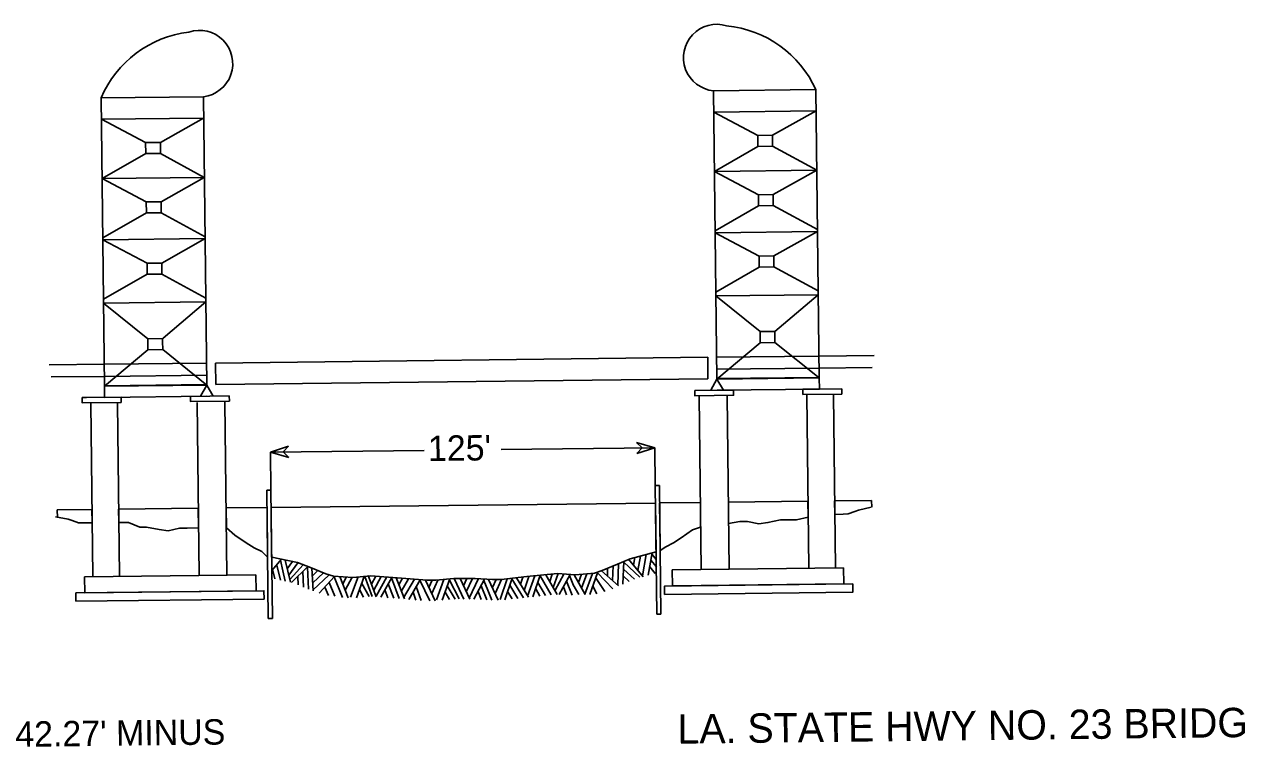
# Model space of a CAD drawing. Extents: x 3683402 to 3721514, y 487807 to 513565.
# Drawn here: x 3690742 to 3695530, y 507301 to 510168 of the extents above; entities that cross this region are included whole.
import ezdxf

# ---------------------------------------------------------------- set-up
doc = ezdxf.new("R2010")
doc.units = 0
doc.layers.add('V-ANNO-SYMB', color=7, linetype='Continuous')

msp = doc.modelspace()

# ---------------------------------------------------------------- linework, layer by layer
at = {"layer": 'V-ANNO-SYMB'}
for p, q in [((3693863.4, 509910.7), (3693460.2, 509906)), ((3693473.4, 508769.8), (3693460.2, 509906)), ((3693876.6, 508774.4), (3693863.4, 509910.7)), ((3691045.2, 509878), (3691448.4, 509882.7)), ((3691058.4, 508741.7), (3691045.2, 509878)), ((3691461.6, 508746.4), (3691448.4, 509882.7)), ((3693864.3, 509826.8), (3693461.1, 509822.1)), ((3693634, 509730.2), (3693461.1, 509822.1)), ((3693864.3, 509826.8), (3693692.1, 509730.8)), ((3691046.2, 509794.1), (3691449.4, 509798.8)), ((3691046.2, 509794.1), (3691220.6, 509702.1)), ((3691278.7, 509702.8), (3691449.4, 509798.8)), ((3691048.9, 509560.2), (3691221.1, 509658.7)), ((3691279.2, 509659.3), (3691452.1, 509564.9)), ((3693634.5, 509686.7), (3693463.8, 509588.3)), ((3693867.1, 509593), (3693692.6, 509687.4)), ((3691048.9, 509560.2), (3691452.1, 509564.9)), ((3691281.4, 509468.9), (3691452.1, 509564.9)), ((3693867.1, 509593), (3693463.8, 509588.3)), ((3693636.7, 509496.3), (3693463.8, 509588.3)), ((3693867.1, 509593), (3693694.8, 509497)), ((3691048.9, 509560.2), (3691223.4, 509468.2)), ((3691051.6, 509326.3), (3691223.9, 509424.8)), ((3691281.9, 509425.5), (3691454.8, 509331)), ((3693637.2, 509452.8), (3693466.6, 509354.4)), ((3693869.8, 509359.1), (3693695.3, 509453.5)), ((3691051.7, 509318.6), (3691454.9, 509323.3)), ((3691284.2, 509227.3), (3691454.9, 509323.3)), ((3693869.9, 509351.4), (3693466.7, 509346.7)), ((3693639.5, 509254.7), (3693466.7, 509346.7)), ((3693869.9, 509351.4), (3693697.6, 509255.4)), ((3691051.7, 509318.6), (3691226.2, 509226.7)), ((3691054.4, 509084.8), (3691226.7, 509183.2)), ((3691284.8, 509183.9), (3691457.6, 509089.4)), ((3693640, 509211.3), (3693469.4, 509112.8)), ((3693872.6, 509117.5), (3693698.1, 509211.9)), ((3693872.8, 509102.3), (3693469.5, 509097.7)), ((3693643.1, 508956.8), (3693469.5, 509097.7)), ((3693872.8, 509102.3), (3693701.2, 508957.5)), ((3691054.6, 509069.6), (3691457.8, 509074.3)), ((3691054.6, 509069.6), (3691229.5, 508928.7)), ((3691290.1, 508931.5), (3691457.8, 509074.3)), ((3693643.6, 508913.3), (3693473.4, 508769.8)), ((3693876.6, 508774.4), (3693701.7, 508914)), ((3691058.4, 508741.7), (3691230, 508885.3)), ((3691288.1, 508886), (3691461.6, 508746.4)), ((3691496.2, 508833.1), (3693436.8, 508855.6)), ((3693436.8, 508855.6), (3691496.2, 508833.1)), ((3693436.8, 508855.6), (3693437.8, 508771.1)), ((3693436.8, 508855.6), (3693437.8, 508771.1)), ((3693469.3, 508856), (3693875.6, 508860.7)), ((3693875.6, 508860.7), (3694092.6, 508863.2)), ((3694092.6, 508863.2), (3693875.6, 508860.7)), ((3691057.4, 508828), (3690840.4, 508825.4)), ((3690840.4, 508825.4), (3691057.4, 508828)), ((3691461.6, 508832.7), (3691057.4, 508828)), ((3691496.2, 508833.1), (3691497.2, 508748.5)), ((3691496.2, 508833.1), (3691497.2, 508748.5)), ((3693469.9, 508808.5), (3693876.1, 508813.3)), ((3693876.1, 508813.3), (3694085.9, 508815.7)), ((3691058, 508780.5), (3690848.2, 508778.1)), ((3691462.2, 508785.2), (3691058, 508780.5)), ((3691462.6, 508748.1), (3691058.4, 508743.4)), ((3691497.2, 508748.5), (3693437.8, 508771.1)), ((3693437.8, 508771.1), (3691497.2, 508748.5)), ((3693473.4, 508769.8), (3693449.2, 508725.5)), ((3693470.3, 508771.5), (3693876.6, 508776.2)), ((3693876.6, 508774.4), (3693473.4, 508769.8)), ((3693473.4, 508769.8), (3693498.6, 508726.1)), ((3693876.6, 508774.4), (3693877.1, 508730.5)), ((3691058.4, 508741.7), (3691461.6, 508746.4)), ((3691058.4, 508741.7), (3691058.9, 508697.7)), ((3691058.9, 508697.7), (3691462.1, 508702.4)), ((3691461.6, 508746.4), (3691437.4, 508702.1)), ((3691461.6, 508746.4), (3691486.9, 508702.7)), ((3693403, 508701), (3693411, 508019.1)), ((3693877.1, 508730.5), (3693473.9, 508725.8)), ((3693513.3, 508702.3), (3693521.2, 508020.4)), ((3693827.2, 508705.9), (3693835.1, 508024)), ((3693932.3, 508707.2), (3693940.3, 508025.3)), ((3693965.5, 508731.5), (3693965.7, 508711)), ((3691004.2, 508673.1), (3691012.2, 507991.2)), ((3691109.4, 508674.3), (3691117.3, 507992.5)), ((3691423.3, 508678), (3691431.2, 507996.1)), ((3691533.5, 508679.3), (3691541.5, 507997.4)), ((3693156.3, 508520.4), (3693178.4, 508498.8)), ((3693228.4, 508499.5), (3693156.3, 508520.4)), ((3693156.3, 508520.4), (3693178.4, 508498.8)), ((3693228.4, 508499.5), (3693156.3, 508520.4)), ((3691783.9, 508505.1), (3691712.8, 508481.9)), ((3691783.9, 508505.1), (3691712.8, 508481.9)), ((3691712.8, 508481.9), (3692318.4, 508488.9)), ((3691712.8, 508481.9), (3691727.6, 508482)), ((3691714.5, 508332.6), (3691712.8, 508481.9)), ((3691712.8, 508481.9), (3691784.9, 508461)), ((3691712.8, 508481.9), (3691784.9, 508461)), ((3691762.8, 508482.5), (3691783.9, 508505.1)), ((3691762.8, 508482.5), (3691783.9, 508505.1)), ((3691784.9, 508461), (3691762.8, 508482.5)), ((3691784.9, 508461), (3691762.8, 508482.5)), ((3692621.9, 508492.4), (3693228.4, 508499.5)), ((3693157.3, 508476.3), (3693228.4, 508499.5)), ((3693157.3, 508476.3), (3693228.4, 508499.5)), ((3693178.4, 508498.8), (3693157.3, 508476.3)), ((3693178.4, 508498.8), (3693157.3, 508476.3)), ((3693230.2, 508350.2), (3693228.4, 508499.5)), ((3691698.5, 508332.4), (3691714.5, 508332.6)), ((3691704.4, 507825.7), (3691698.5, 508332.4)), ((3691720.4, 507825.9), (3691714.5, 508332.6)), ((3693246.2, 508350.4), (3693230.2, 508350.2)), ((3693236.1, 507843.5), (3693230.2, 508350.2)), ((3693252.1, 507843.7), (3693246.2, 508350.4)), ((3691715.3, 508263.8), (3693231, 508281.4)), ((3693231, 508281.4), (3691715.3, 508263.8)), ((3693233.2, 508088.5), (3693231, 508281.4)), ((3693247, 508281.6), (3693407.9, 508283.5)), ((3693247, 508281.6), (3693407.9, 508283.5)), ((3693249, 508103.5), (3693247, 508281.6)), ((3693407.9, 508283.5), (3693409, 508186.4)), ((3693518.2, 508284.7), (3693832, 508288.4)), ((3693832, 508288.4), (3693518.2, 508284.7)), ((3693518.2, 508284.7), (3693519.1, 508200.3)), ((3693832.7, 508225.3), (3693832, 508288.4)), ((3693937.2, 508289.6), (3694083.2, 508291.3)), ((3694083.2, 508291.3), (3693937.2, 508289.6)), ((3693937.2, 508289.6), (3693937.8, 508236.7)), ((3694083.5, 508264.4), (3694083.2, 508291.3)), ((3690872.5, 508254), (3691009.1, 508255.6)), ((3690872.5, 508254), (3691009.1, 508255.6)), ((3690872.8, 508223.8), (3690872.5, 508254)), ((3691009.1, 508255.6), (3691009.7, 508203.5)), ((3691114.3, 508256.8), (3691428.1, 508260.4)), ((3691428.1, 508260.4), (3691114.3, 508256.8)), ((3691114.3, 508256.8), (3691114.9, 508204.2)), ((3691429, 508183.1), (3691428.1, 508260.4)), ((3691538.4, 508261.7), (3691699.3, 508263.6)), ((3691699.3, 508263.6), (3691538.4, 508261.7)), ((3691538.4, 508261.7), (3691539.3, 508183.2)), ((3691701.6, 508069.3), (3691699.3, 508263.6)), ((3691715.3, 508263.8), (3691717.6, 508068)), ((3693194.7, 508078.3), (3693179.4, 507994.2)), ((3693218.1, 508084.5), (3693202.4, 507996.4)), ((3693217.2, 508079), (3693234.1, 508058.7)), ((3693249, 508103.5), (3693249.2, 508093.6)), ((3691755.9, 508060), (3691718.2, 508015.4)), ((3691738.3, 508036.3), (3691752, 507977.7)), ((3691752.6, 508055.5), (3691762.2, 508014.3)), ((3691771.2, 508056.7), (3691791.3, 507969.5)), ((3691800.1, 508050.7), (3691779.2, 508022.3)), ((3691821.1, 508046.2), (3691785, 507997.4)), ((3691841.7, 508038.1), (3691790.6, 507981.3)), ((3691860.6, 508030.8), (3691796.1, 507968.3)), ((3691858.5, 508029.1), (3691863, 507942.4)), ((3693063.5, 508033.3), (3693062.1, 507975.3)), ((3693084.8, 508042.5), (3693082.4, 507957.4)), ((3693105.6, 508051.1), (3693101.9, 507961.6)), ((3693105.5, 508048.6), (3693169.5, 507989.6)), ((3693124.9, 508060), (3693182.1, 507991)), ((3693150, 508066.6), (3693144.7, 508036.3)), ((3693172.2, 508072.4), (3693161.9, 508015.2)), ((3693208.4, 508030), (3693230, 508003.6)), ((3693212.9, 508055.5), (3693234.5, 508029.6)), ((3690979.9, 507990.9), (3691655.6, 507998.7)), ((3690979.9, 507990.9), (3690980.6, 507927.4)), ((3691655.6, 507998.7), (3691656.3, 507935.3)), ((3691722.8, 508015.6), (3691730.3, 507982.3)), ((3691762.2, 508014.3), (3691771.5, 507973.6)), ((3691820.5, 507992.2), (3691822.5, 507958.4)), ((3691839.9, 508010.9), (3691843.7, 507950.2)), ((3691876.5, 508024.5), (3691881.5, 507934.9)), ((3691899.9, 508015.1), (3691878.3, 507994.4)), ((3691921.9, 508006.2), (3691879.7, 507966.4)), ((3691943.5, 507997.5), (3691881.3, 507939.3)), ((3691965.2, 507991.6), (3691904.5, 507925.7)), ((3691964.2, 507990.2), (3691996.4, 507909.3)), ((3691986.5, 507991.2), (3692019.8, 507908)), ((3692012.4, 507989.8), (3691998.1, 507962.6)), ((3692035.4, 507988.6), (3692008, 507937.2)), ((3692058.5, 507990.2), (3692029, 507910)), ((3692082.7, 507992.2), (3692051.9, 507908.1)), ((3692084.6, 507992.3), (3692114.3, 507913.4)), ((3692098.2, 507995), (3692129.9, 507911.3)), ((3692127.7, 507992.9), (3692110.8, 507962)), ((3692149.1, 507991.4), (3692120, 507938)), ((3692171.2, 507989.8), (3692129.4, 507913.8)), ((3692191.4, 507988.3), (3692148, 507909.7)), ((3692189.9, 507985.9), (3692220.8, 507904.8)), ((3692208.5, 507987.1), (3692240.7, 507903.3)), ((3692233.7, 507985.3), (3692219.4, 507959)), ((3692257.3, 507983.1), (3692228.5, 507932.7)), ((3692280.4, 507981.1), (3692237.9, 507907.3)), ((3692420, 507982.2), (3692390.1, 507897.8)), ((3692438.5, 507981.3), (3692474.8, 507902.2)), ((3692460.7, 507983.5), (3692498.3, 507902.1)), ((3692486.7, 507983.4), (3692473.7, 507955.5)), ((3692509.7, 507983.4), (3692485, 507930.7)), ((3692532.9, 507983.3), (3692496.5, 507905.9)), ((3692557.1, 507981.3), (3692515.2, 507902.2)), ((3692645.7, 507982.6), (3692618.3, 507900.4)), ((3692665.8, 507984.9), (3692637.4, 507899.7)), ((3692664.8, 507982.2), (3692709.9, 507908.1)), ((3692682.8, 507986.8), (3692729.7, 507910.3)), ((3692707.9, 507989.6), (3692698.6, 507961.1)), ((3692731.5, 507992.2), (3692713.2, 507937.1)), ((3692754.6, 507994.3), (3692726.2, 507914)), ((3692776.9, 507996.4), (3692747.2, 507912)), ((3692776.2, 507994.1), (3692820.1, 507918.9)), ((3692798, 507998.4), (3692843.4, 507921.1)), ((3692823.9, 508000.9), (3692813.8, 507971.8)), ((3692846.8, 508003.1), (3692827.4, 507948.3)), ((3692870, 508001.3), (3692835.7, 507937.6)), ((3692894.1, 507999.9), (3692851.8, 507921)), ((3692891.6, 507995), (3692907.2, 507955.6)), ((3692909.8, 507998.2), (3692953.6, 507920.1)), ((3692939.2, 508000.5), (3692927.1, 507967.4)), ((3692960.6, 508002.2), (3692939.7, 507945.1)), ((3692982.7, 508003.9), (3692952.6, 507922.6)), ((3693002.8, 508005.5), (3692971.7, 507921.3)), ((3692994.8, 507987.4), (3693031.2, 507932)), ((3693001.9, 508005.7), (3693062.2, 507943.3)), ((3693018.5, 508014), (3693085.6, 507954.4)), ((3693041.7, 508024), (3693041.1, 507994)), ((3693103.7, 507994.8), (3693127.8, 507972.3)), ((3693104.4, 508020.8), (3693147.8, 507980.6)), ((3693972.5, 508025.6), (3693296.8, 508017.8)), ((3693296.8, 508017.8), (3693297.6, 507954.4)), ((3693972.5, 508025.6), (3693973.3, 507962.2)), ((3690980.6, 507927.4), (3691656.3, 507935.3)), ((3691927.4, 507949.9), (3691941.7, 507916.4)), ((3691944.6, 507968.6), (3691966.4, 507913.6)), ((3692063.7, 507940.2), (3692080.3, 507910.5)), ((3692072.5, 507964.5), (3692102.5, 507912.3)), ((3692164.3, 507939.7), (3692176.2, 507907.9)), ((3692177.4, 507963.3), (3692198.9, 507906.3)), ((3692302.8, 507979.1), (3692258.2, 507901.5)), ((3692287.8, 507952.8), (3692307.7, 507897.1)), ((3692301.6, 507976.9), (3692341.4, 507896)), ((3692323.9, 507976.6), (3692362.7, 507895.8)), ((3692349.9, 507976.9), (3692337.3, 507948.8)), ((3692372.8, 507977.2), (3692349, 507924.2)), ((3692395.9, 507979.9), (3692367.1, 507899.5)), ((3692410.2, 507954.4), (3692440.6, 507902.5)), ((3692418.2, 507976.9), (3692457.5, 507903.7)), ((3692543.3, 507955.3), (3692565.8, 507899.5)), ((3692554.5, 507976.4), (3692570.4, 507937.2)), ((3692570.4, 507937.2), (3692585.7, 507898.4)), ((3692572.7, 507979.5), (3692611.2, 507898.7)), ((3692602.2, 507979.9), (3692587.9, 507947.7)), ((3692623.6, 507980.1), (3692599, 507924.6)), ((3692656.6, 507957.7), (3692688.1, 507905.6)), ((3692758.7, 507943.2), (3692775.1, 507914.6)), ((3692767, 507967.9), (3692796.7, 507916.7)), ((3692868, 507951.2), (3692880.2, 507919.3)), ((3692880.2, 507973.9), (3692902.4, 507918)), ((3692906.1, 507958.5), (3692929, 507921.4)), ((3692983.4, 507953.4), (3692999.9, 507923.8)), ((3693973.3, 507962.2), (3693297.6, 507954.4)), ((3692275.1, 507930.1), (3692286.1, 507899)), ((3692401.5, 507930), (3692418.5, 507900.4)), ((3692531.2, 507932.4), (3692543.6, 507900.7)), ((3692648, 507932.1), (3692665.5, 507903.1)), ((3693252.1, 507843.7), (3693236.1, 507843.5)), ((3691704.4, 507825.7), (3691720.4, 507825.9))]:
    msp.add_line(p, q, dxfattribs=at)
for points in [[(3693692.1, 509730.8), (3693634, 509730.2), (3693634.5, 509686.7), (3693692.6, 509687.4), (3693692.1, 509730.8)], [(3691278.8, 509691.8), (3691279.2, 509659.3), (3691221.1, 509658.7), (3691220.6, 509702.1), (3691278.7, 509702.8), (3691278.8, 509691.8)], [(3691281.4, 509468.9), (3691281.9, 509425.5), (3691223.9, 509424.8), (3691223.4, 509468.2), (3691281.4, 509468.9)], [(3693694.8, 509497), (3693636.7, 509496.3), (3693637.2, 509452.8), (3693695.3, 509453.5), (3693694.8, 509497)], [(3691284.2, 509227.3), (3691284.8, 509183.9), (3691226.7, 509183.2), (3691226.2, 509226.7), (3691284.2, 509227.3)], [(3693697.6, 509255.4), (3693639.5, 509254.7), (3693640, 509211.3), (3693698.1, 509211.9), (3693697.6, 509255.4)], [(3693701.2, 508957.5), (3693643.1, 508956.8), (3693643.6, 508913.3), (3693701.7, 508914), (3693701.2, 508957.5)], [(3691287.8, 508918), (3691288.1, 508886), (3691230, 508885.3), (3691229.5, 508928.7), (3691287.6, 508929.4), (3691287.8, 508918)], [(3691550.5, 508703.4), (3691550.8, 508682.9), (3691397.6, 508681.1), (3691397.4, 508701.7), (3691550.5, 508703.4)], [(3693385.5, 508724.8), (3693385.7, 508704.2), (3693538.9, 508706), (3693538.6, 508726.6), (3693385.5, 508724.8)], [(3693965.7, 508711), (3693812.5, 508709.2), (3693812.3, 508729.7), (3693965.5, 508731.5)], [(3690987.6, 508696.9), (3690970.6, 508696.7), (3690970.8, 508676.1), (3691123.9, 508677.9), (3691123.7, 508698.5), (3690987.6, 508696.9)], [(3690865.3, 508227), (3690915.8, 508217.5), (3690931, 508212.7), (3690956.3, 508202.9), (3690976.4, 508203.1), (3691009.7, 508203.5)], [(3691009.7, 508203.5), (3690976.4, 508203.1), (3690956.3, 508202.9), (3690931, 508212.7), (3690915.8, 508217.5), (3690865.3, 508227)], [(3693832.7, 508225.3), (3693786.7, 508214.7), (3693749.5, 508215.2), (3693724.3, 508214.9), (3693674, 508204.2), (3693638.8, 508198.7), (3693593.3, 508208.3), (3693563.1, 508208), (3693519.1, 508200.3)], [(3693519.1, 508200.3), (3693563.1, 508208), (3693593.3, 508208.3), (3693638.8, 508198.7), (3693674, 508204.2), (3693724.3, 508214.9), (3693749.5, 508215.2), (3693786.7, 508214.7), (3693832.7, 508225.3)], [(3694081.7, 508264.4), (3694031.4, 508253.8), (3694016.3, 508248.5), (3693991.2, 508238.2), (3693971.1, 508237.9), (3693938.2, 508236.7)], [(3693938.2, 508236.7), (3693971.1, 508237.9), (3693991.2, 508238.2), (3694016.3, 508248.5), (3694031.4, 508253.8), (3694081.7, 508264.4)], [(3691114.9, 508204.2), (3691152.8, 508205.2), (3691198.4, 508185.5), (3691223.6, 508185.8), (3691274.2, 508176.3), (3691309.5, 508171.7), (3691354.8, 508182.3), (3691385, 508182.6), (3691429, 508183.1)], [(3691114.9, 508204.2), (3691152.8, 508205.2), (3691198.4, 508185.5), (3691223.6, 508185.8), (3691274.2, 508176.3), (3691309.5, 508171.7), (3691354.8, 508182.3), (3691385, 508182.6), (3691429, 508183.1)], [(3691539.3, 508183.2), (3691571.8, 508154.5), (3691617.6, 508124.8), (3691648, 508105), (3691678.5, 508090.2), (3691699.9, 508069.2)], [(3691539.3, 508183.2), (3691571.8, 508154.5), (3691617.6, 508124.8), (3691648, 508105), (3691678.5, 508090.2), (3691699.9, 508069.2)], [(3693409, 508186.4), (3693376.9, 508175.5), (3693331.9, 508144.7), (3693301.9, 508124.2), (3693271.8, 508108.7), (3693249.2, 508093.7)], [(3693409, 508186.4), (3693376.9, 508175.5), (3693331.9, 508144.7), (3693301.9, 508124.2), (3693271.8, 508108.7), (3693249.2, 508093.7)], [(3693233.2, 508088.5), (3693131.2, 508061.7), (3693081.1, 508040.9), (3693020.9, 508015), (3692990.8, 508004.6), (3692915.2, 507998.6), (3692844.6, 508002.9), (3692723.7, 507991.4), (3692623, 507980.1), (3692587.8, 507979.7), (3692520, 507983.3), (3692435.6, 507983.6)], [(3692435.6, 507983.6), (3692520, 507983.3), (3692587.8, 507979.7), (3692623, 507980.1), (3692723.7, 507991.4), (3692844.6, 508002.9), (3692915.2, 507998.6), (3692990.8, 508004.6), (3693020.9, 508015), (3693081.1, 508040.9), (3693131.2, 508061.7), (3693233.2, 508088.5)], [(3692435.6, 507983.6), (3692520, 507983.3), (3692587.8, 507979.7), (3692623, 507980.1), (3692723.7, 507991.4), (3692844.6, 508002.9), (3692915.2, 507998.6), (3692990.8, 508004.6), (3693020.9, 508015), (3693081.1, 508040.9), (3693131.2, 508061.7), (3693233.2, 508088.5)], [(3692435.6, 507983.6), (3692520, 507983.3), (3692587.8, 507979.7), (3692623, 507980.1), (3692723.7, 507991.4), (3692844.6, 508002.9), (3692915.2, 507998.6), (3692990.8, 508004.6), (3693020.9, 508015), (3693081.1, 508040.9), (3693131.2, 508061.7), (3693233.2, 508088.5)], [(3692435.6, 507983.6), (3692520, 507983.3), (3692587.8, 507979.7), (3692623, 507980.1), (3692723.7, 507991.4), (3692844.6, 508002.9), (3692915.2, 507998.6), (3692990.8, 508004.6), (3693020.9, 508015), (3693081.1, 508040.9), (3693131.2, 508061.7), (3693233.2, 508088.5)], [(3691717.8, 508068), (3691820.1, 508046.4), (3691870.8, 508026.9), (3691931.5, 508002.3), (3691961.9, 507992.6), (3692037.6, 507988.4), (3692108.1, 507994.3), (3692229.1, 507985.6), (3692330.1, 507976.7), (3692365.4, 507977.1), (3692435.6, 507983.6)], [(3691717.8, 508068), (3691820.1, 508046.4), (3691870.8, 508026.9), (3691931.5, 508002.3), (3691961.9, 507992.6), (3692037.6, 507988.4), (3692108.1, 507994.3), (3692229.1, 507985.6), (3692330.1, 507976.7), (3692365.4, 507977.1), (3692435.6, 507983.6)], [(3691717.8, 508068), (3691820.1, 508046.4), (3691870.8, 508026.9), (3691931.5, 508002.3), (3691961.9, 507992.6), (3692037.6, 507988.4), (3692108.1, 507994.3), (3692229.1, 507985.6), (3692330.1, 507976.7), (3692365.4, 507977.1), (3692435.6, 507983.6)], [(3690945.9, 507894.1), (3690945.5, 507927), (3691687.3, 507935.6), (3691687.7, 507902.7), (3690945.9, 507894.1)], [(3694008.4, 507962.6), (3693266.5, 507954), (3693266.9, 507921), (3694008.7, 507929.7), (3694008.4, 507962.6)]]:
    msp.add_lwpolyline(points, dxfattribs=at)
for centre, radius, start, end in [((3691443.5, 509707.8), 433.1, 96.9451, 156.8649), ((3691432.9, 510013.1), 131.4, 276.8024, 108.5355), ((3693472.7, 510036.8), 131.4, 72.7965, 264.5296), ((3693469.2, 509731.4), 433.1, 24.4671, 84.3869)]:
    msp.add_arc(centre, radius, start, end, dxfattribs=at)

# ---------------------------------------------------------------- texts
for s, height, p in [(" 125'", 100, (3692297.3, 508446.3)), ('LA. STATE HWY NO. 23 BRIDGE', 115.999, (3693318.2, 507332.6)), ("VERTICAL CLEARANCE = 42.27' MINUS ", 100, (3689046.5, 507300.7))]:
    msp.add_text(s, height=height, rotation=0.666, dxfattribs=at).set_placement(p)

doc.saveas('drawing.dxf')
